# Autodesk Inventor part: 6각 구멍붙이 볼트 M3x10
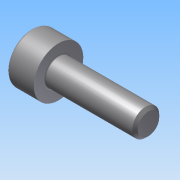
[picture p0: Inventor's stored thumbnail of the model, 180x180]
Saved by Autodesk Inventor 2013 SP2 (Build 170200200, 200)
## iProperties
Created: 2025-07
Part Number: 6각 구멍붙이 볼트 M3x10
Material: Generic
Document SubType Name: Modeling
Designer: a
Density: 1 g/cm^3
Author: a
변환 표준: STEP AP214IS
전처리기: Build: 200, Release: 2013 SP2 Update 6 - Date: Thu 07/17/2014
전송 단위: 밀리미터
불확실성: 0.01
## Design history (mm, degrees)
node "6각 구멍붙이 볼트 M3x101"
body "Solid1"
node "기준1"
